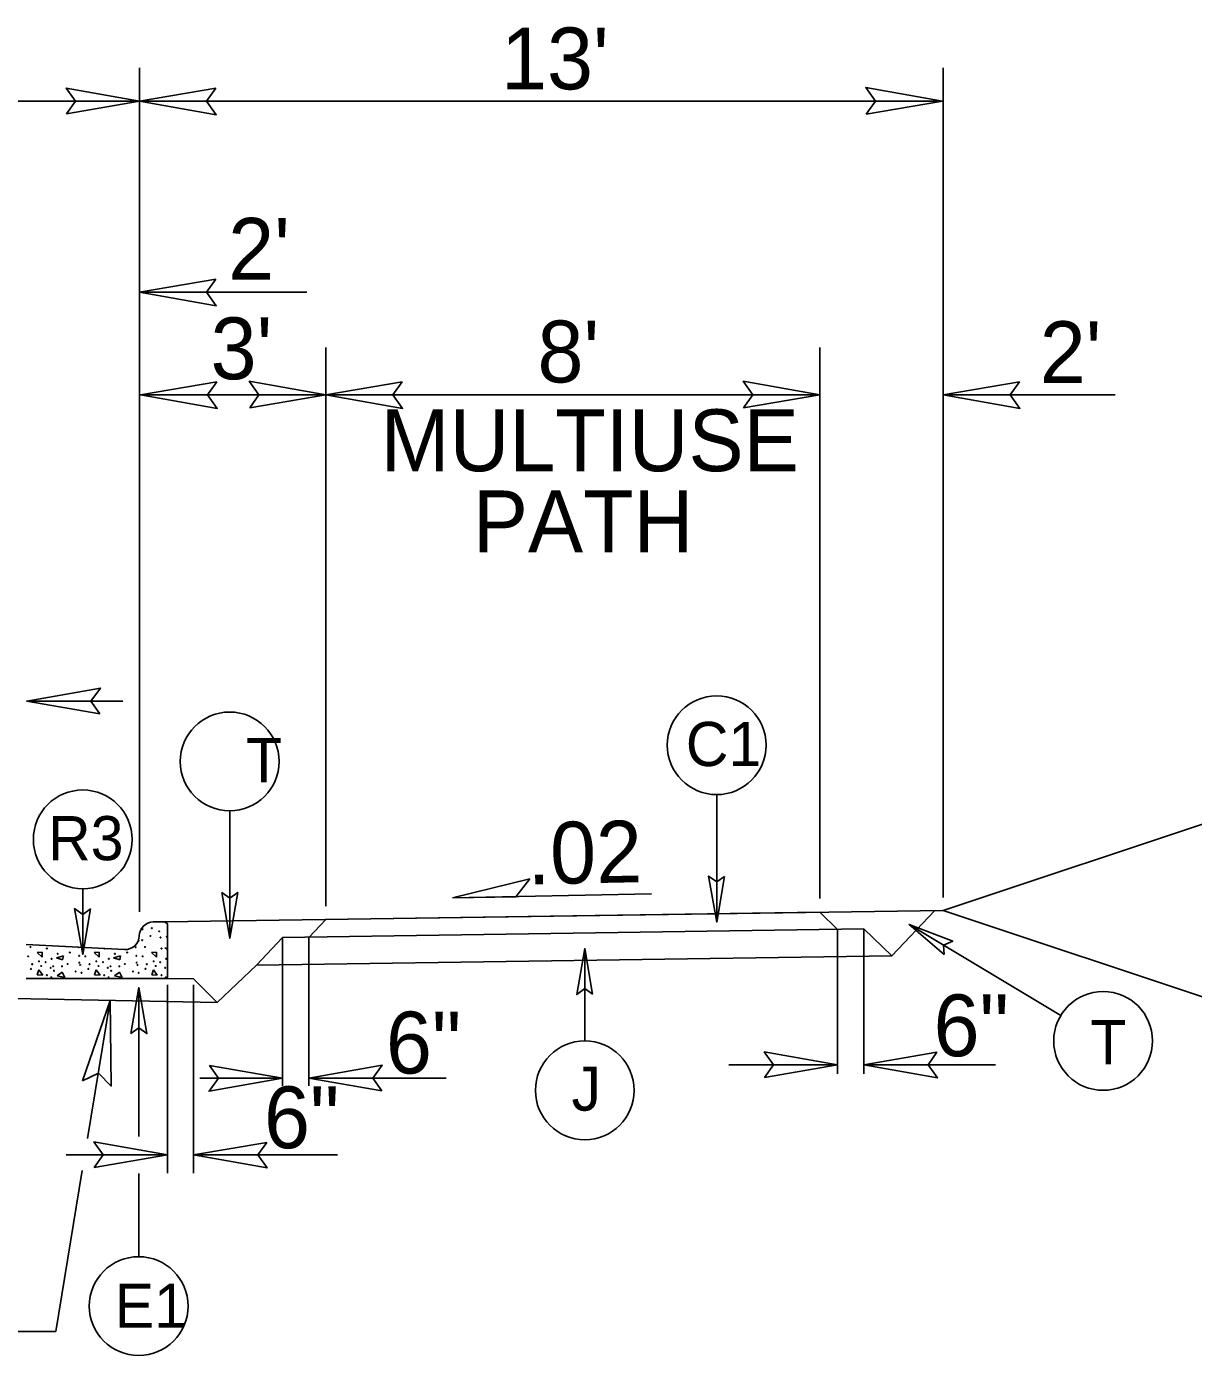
# Model space of a CAD drawing. Extents: x 958711 to 962106, y 831169 to 840840.
# Drawn here: x 961372.3 to 961519.5, y 834991.2 to 835158.8 of the extents above; entities that cross this region are included whole.
import ezdxf

# ---------------------------------------------------------------- set-up
doc = ezdxf.new("R2010")
doc.units = 0
for name, color, linetype in [('Old_Level_1', 7, 'Continuous'), ('Old_Level_11', 7, 'Continuous'), ('Old_Level_3', 7, 'Continuous'), ('Prop Dimension Text', 7, 'Continuous'), ('Typical ID Circle CELL', 7, 'Continuous'), ('Typical Terminator CELL', 7, 'Continuous'), ('Typical Text ID Circle CELL', 7, 'Continuous')]:
    doc.layers.add(name, color=color, linetype=linetype)

msp = doc.modelspace()

# ---------------------------------------------------------------- linework, layer by layer
at = {"layer": 'Old_Level_1'}
for p, q in [((961386.54, 835047.12), (961386.54, 835153.58)), ((961487.93, 835048.91), (961487.93, 835153.6)), ((961171.04, 835149.39), (961386.54, 835149.39)), ((961487.81, 835149.39), (961386.54, 835149.39)), ((961407.65, 835125.28), (961386.54, 835125.28)), ((961410.03, 835047.82), (961410.03, 835118.3)), ((961472.35, 835048.79), (961472.35, 835118.3)), ((961410.03, 835112.34), (961386.66, 835112.34)), ((961472.35, 835112.34), (961410.03, 835112.34)), ((961487.93, 835112.34), (961509.62, 835112.34)), ((961372.3, 835073.7), (961384.42, 835073.7)), ((961487.93, 835047.29), (961565.11, 835073.02)), ((961451.12, 835049.38), (961426.01, 835048.87)), ((961487.93, 835047.29), (961389.73, 835045.84)), ((961486.85, 835047.27), (961481.45, 835041.59)), ((961565.11, 835021.56), (961487.93, 835047.29)), ((961410.03, 835046.14), (961407.92, 835043.93)), ((961410.03, 835046.14), (961472.35, 835047.06)), ((961472.35, 835047.06), (961474.6, 835044.91)), ((961404.57, 835043.88), (961477.9, 835044.96)), ((961407.87, 835025.16), (961407.87, 835043.93)), ((961474.6, 835026.69), (961474.6, 835044.91)), ((961477.9, 835044.96), (961481.45, 835041.59)), ((961477.9, 835026.69), (961477.9, 835044.88)), ((961404.57, 835043.88), (961401.27, 835040.41)), ((961404.57, 835025.16), (961404.57, 835043.88)), ((961401.27, 835040.41), (961481.45, 835041.59)), ((961396.32, 835035.68), (961401.27, 835040.41)), ((961390.05, 835038.71), (961393.35, 835038.65)), ((961390.05, 835014.16), (961390.05, 835037.91)), ((961393.35, 835038.65), (961396.32, 835035.68)), ((961393.35, 835014.16), (961393.35, 835037.91)), ((961365.67, 835036.3), (961396.32, 835035.68)), ((961379.97, 835018.52), (961382.84, 835035.94)), ((961474.6, 835027.82), (961460.87, 835027.82)), ((961494.5, 835027.82), (961477.9, 835027.82)), ((961394.15, 835026.13), (961404.57, 835026.13)), ((961407.87, 835026.13), (961425.2, 835026.13)), ((961390.05, 835016.45), (961377.28, 835016.45)), ((961411.49, 835016.45), (961393.35, 835016.45)), ((961375.95, 834994.17), (961379.3, 835014.51)), ((961375.95, 834994.17), (961315.04, 834994.17))]:
    msp.add_line(p, q, dxfattribs=at)
msp.add_arc((961389.73, 835042.25), 0.309, 0, 90, dxfattribs=at)
at = {"layer": 'Old_Level_11'}
for p, q in [((961435.75, 835051.29), (961426.01, 835048.87)), ((961434.01, 835049.03), (961435.75, 835051.29)), ((961426.01, 835048.87), (961434.01, 835049.03))]:
    msp.add_line(p, q, dxfattribs=at)
for points in [[(961396.15, 835151.04), (961386.54, 835149.39), (961396.21, 835147.67), (961394.98, 835149.39)], [(961478.2, 835147.73), (961487.81, 835149.39), (961478.15, 835151.1), (961479.37, 835149.39)], [(961396.15, 835126.94), (961386.54, 835125.28), (961396.21, 835123.57), (961394.98, 835125.28)], [(961396.27, 835113.99), (961386.66, 835112.34), (961396.33, 835110.62), (961395.1, 835112.34)], [(961400.42, 835110.68), (961410.03, 835112.34), (961400.37, 835114.05), (961401.59, 835112.34)], [(961419.64, 835113.99), (961410.03, 835112.34), (961419.7, 835110.62), (961418.47, 835112.34)], [(961462.74, 835110.68), (961472.35, 835112.34), (961462.69, 835114.05), (961463.91, 835112.34)], [(961497.54, 835113.99), (961487.93, 835112.34), (961497.6, 835110.62), (961496.37, 835112.34)], [(961379.32, 835025.8), (961382.84, 835035.94), (961382.96, 835025.15), (961381.33, 835026.78)]]:
    msp.add_lwpolyline(points, close=True, dxfattribs=at)
at = {"layer": 'Old_Level_3'}
for p, q in [((961389.73, 835045.84), (961388.26, 835045.84)), ((961390.05, 835042.28), (961390.05, 835045.53)), ((961384.64, 835042.38), (961372.24, 835042.99)), ((961384.64, 835042.38), (961384.64, 835042.38)), ((961386.46, 835043.48), (961386.3, 835043.52)), ((961386.34, 835043.64), (961386.46, 835043.48)), ((961390.05, 835038.71), (961390.05, 835042.28)), ((961373.6, 835042), (961374.22, 835042.03)), ((961374.22, 835041.4), (961373.6, 835042)), ((961374.22, 835042.03), (961374.22, 835041.4)), ((961376.03, 835041.34), (961376.92, 835041.59)), ((961376.82, 835041.07), (961376.03, 835041.34)), ((961376.92, 835041.59), (961376.82, 835041.07)), ((961380.82, 835042), (961381.45, 835042.03)), ((961381.45, 835041.4), (961380.82, 835042)), ((961381.45, 835042.03), (961381.45, 835041.4)), ((961383.26, 835041.34), (961384.14, 835041.59)), ((961384.05, 835041.07), (961383.26, 835041.34)), ((961384.14, 835041.59), (961384.05, 835041.07)), ((961388.05, 835042), (961388.68, 835042.03)), ((961388.68, 835041.4), (961388.05, 835042)), ((961388.68, 835042.03), (961388.68, 835041.4)), ((961373.82, 835039.82), (961373.63, 835039.16)), ((961373.63, 835039.16), (961374.32, 835039.12)), ((961374.32, 835039.12), (961373.82, 835039.82)), ((961376.75, 835039.49), (961376.15, 835039.06)), ((961376.15, 835039.06), (961377.12, 835038.84)), ((961377.12, 835038.84), (961376.75, 835039.49)), ((961381.05, 835039.82), (961380.86, 835039.16)), ((961380.86, 835039.16), (961381.54, 835039.12)), ((961381.54, 835039.12), (961381.05, 835039.82)), ((961383.98, 835039.49), (961383.38, 835039.06)), ((961383.38, 835039.06), (961384.35, 835038.84)), ((961384.35, 835038.84), (961383.98, 835039.49)), ((961388.27, 835039.82), (961388.09, 835039.16)), ((961388.09, 835039.16), (961388.77, 835039.12)), ((961388.77, 835039.12), (961388.27, 835039.82)), ((961372.24, 835038.71), (961390.05, 835038.71))]:
    msp.add_line(p, q, dxfattribs=at)
for centre in [(961386.89, 835044.94), (961387.91, 835044.08), (961388.08, 835045.07), (961389, 835044.67), (961389.17, 835043.88), (961389.98, 835043.98), (961372.76, 835042.69), (961374.84, 835042.49), (961386.03, 835042.66), (961386.85, 835043.55), (961387.22, 835042.69), (961389.3, 835042.49), (961372.47, 835041.5), (961372.99, 835040.51), (961373.85, 835040.87), (961374.68, 835040.77), (961375.43, 835041.2), (961376.19, 835041.83), (961377.45, 835040.54), (961377.74, 835042), (961378.9, 835041.57), (961378.93, 835040.71), (961379.69, 835041.5), (961380.22, 835040.51), (961381.08, 835040.87), (961381.91, 835040.77), (961382.66, 835041.2), (961383.42, 835041.83), (961384.67, 835040.54), (961384.97, 835042), (961386.13, 835041.57), (961386.16, 835040.71), (961386.92, 835041.5), (961387.45, 835040.51), (961388.31, 835040.87), (961389.13, 835040.77), (961389.88, 835041.2), (961372.83, 835039.92), (961374.12, 835040.28), (961374.84, 835039.13), (961375.31, 835040.05), (961375.4, 835038.86), (961375.63, 835040.25), (961375.73, 835039.69), (961376.75, 835040.25), (961378.47, 835039.59), (961379.03, 835040.42), (961379.2, 835039.43), (961380.06, 835039.92), (961381.35, 835040.28), (961382.07, 835039.13), (961382.53, 835040.05), (961382.63, 835038.86), (961382.86, 835040.25), (961382.95, 835039.69), (961383.98, 835040.25), (961385.7, 835039.59), (961386.26, 835040.42), (961386.42, 835039.43), (961387.28, 835039.92), (961388.57, 835040.28), (961389.3, 835039.13), (961389.76, 835040.05), (961389.85, 835038.86)]:
    msp.add_circle(centre, 0.0464, dxfattribs=at)
for centre, radius, start, end in [((961388.26, 835044.06), 1.78, 90, 178.9266), ((961389.73, 835045.53), 0.309, 0, 90), ((961389.85, 835045.76), 0.0464, 169.6531, 280.3469), ((961384.73, 835044.13), 1.76, 267.1376, 358.9266), ((961378.8, 835042.66), 0.0464, 164.1199, 10.1626), ((961382.07, 835042.49), 0.0464, 162.062, 12.2205), ((961390.08, 835040.25), 0.0464, 150.4173, 209.5827)]:
    msp.add_arc(centre, radius, start, end, dxfattribs=at)
at = {"layer": 'Typical ID Circle CELL'}
for p, q in [((961459.34, 835061.92), (961459.34, 835045.83)), ((961397.9, 835059.87), (961397.9, 835043.78)), ((961379.36, 835050.03), (961379.36, 835041.74)), ((961502.75, 835034.05), (961483.62, 835045.54)), ((961442.7, 835030.83), (961442.7, 835042.49)), ((961386.42, 835018.79), (961386.42, 835037.56)), ((961386.42, 835003.62), (961386.42, 835014.11))]:
    msp.add_line(p, q, dxfattribs=at)
for centre in [(961459.34, 835068.14), (961397.9, 835066.09), (961379.36, 835056.26), (961508.09, 835030.84), (961442.7, 835024.6), (961386.42, 834997.39)]:
    msp.add_circle(centre, 6.23, dxfattribs=at)
at = {"layer": 'Typical Terminator CELL'}
for points in [[(961377.32, 835147.8), (961386.54, 835149.39), (961377.27, 835151.03), (961378.45, 835149.39)], [(961381.53, 835072.11), (961372.3, 835073.7), (961381.58, 835075.34), (961380.4, 835073.7)], [(961460.33, 835051.59), (961459.34, 835045.83), (961458.32, 835051.63), (961459.34, 835050.89)], [(961396.91, 835049.55), (961397.9, 835043.78), (961398.92, 835049.58), (961397.9, 835048.84)], [(961380.35, 835047.5), (961379.36, 835041.74), (961378.33, 835047.53), (961379.36, 835046.79)], [(961488.05, 835041.72), (961483.62, 835045.54), (961489.12, 835043.43), (961487.96, 835042.93)], [(961443.69, 835036.72), (961442.7, 835042.49), (961441.68, 835036.69), (961442.7, 835037.43)], [(961385.43, 835031.79), (961386.42, 835037.56), (961387.45, 835031.76), (961386.42, 835032.5)], [(961465.38, 835026.23), (961474.6, 835027.82), (961465.33, 835029.46), (961466.51, 835027.82)], [(961487.13, 835029.41), (961477.9, 835027.82), (961487.18, 835026.18), (961486, 835027.82)], [(961395.35, 835027.72), (961404.57, 835026.13), (961395.3, 835024.49), (961396.47, 835026.13)], [(961417.09, 835024.54), (961407.87, 835026.13), (961417.14, 835027.77), (961415.97, 835026.13)], [(961380.82, 835014.86), (961390.05, 835016.45), (961380.77, 835018.09), (961381.95, 835016.45)], [(961402.57, 835018.04), (961393.35, 835016.45), (961402.62, 835014.81), (961401.44, 835016.45)]]:
    msp.add_lwpolyline(points, close=True, dxfattribs=at)

# ---------------------------------------------------------------- texts
at = {"layer": 'Old_Level_3'}
for s, p in [("13'", (961432.13, 835150.87)), ("2'", (961397.71, 835126.85)), ("3'", (961395.49, 835114.3)), ("8'", (961436.73, 835113.9)), ("2'", (961500.09, 835113.81)), ('MULTIUSE', (961416.95, 835102.7)), ('PATH', (961428.57, 835092.47))]:
    msp.add_text(s, height=7.801, dxfattribs=at).set_placement(p)
at = {"layer": 'Prop Dimension Text'}
for s, rotation, p in [('.02', 1.1839, (961435.5, 835050.57)), ('6"', 0, (961486.7, 835028.9)), ('6"', 0, (961417.61, 835026.73)), ('6"', 0, (961402.23, 835017.3))]:
    msp.add_text(s, height=7.801, rotation=rotation, dxfattribs=at).set_placement(p)
at = {"layer": 'Typical Text ID Circle CELL'}
for s, height, p in [('C1', 5.572, (961455.44, 835065.51)), ('R3', 5.572, (961374.98, 835053.63)), ('T', 5.57, (961506.48, 835027.9)), ('J', 5.57, (961441.02, 835022.04)), ('E1', 5.572, (961383.39, 834994.65))]:
    msp.add_text(s, height=height, dxfattribs=at).set_placement(p)
msp.add_text('T', height=5.57, rotation=360, dxfattribs=at).set_placement((961399.94, 835063.46))

doc.saveas('drawing.dxf')
